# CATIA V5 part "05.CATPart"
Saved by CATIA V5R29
Part number: 05
Bounding box of the stored display mesh (mm): x -7.47 to 7.47, y 0 to 80, z -7.47 to 7.47
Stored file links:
  C:\Users\FERIDUN\Desktop\montaj3\05.CATPart
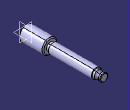
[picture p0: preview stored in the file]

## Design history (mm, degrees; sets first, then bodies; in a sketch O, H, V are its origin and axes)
Body1 (main body)
  Sketch1 on yz-plane, origin (0, 0, 0), H (0, 1, 0), V (0, 0, 1)
    line L1 (0, 0) -> (0, 7.5)
    line L2 (0, 7.5) -> (25, 7.5)
    line L3 (25, 7.5) -> (25, 4)
    line L4 (25, 4) -> (28, 4)
    line L5 (28, 4) -> (28, 5)
    arc A1 centre (76, 4) radius 2 from (74, 4) to (78, 4) ccw
    point P7 (76, 4)
    line L6 (78, 4) -> (80, 4)
    line L7 (80, 4) -> (80, 0)
    point P10 (80, 0)
    axis line L8 (0, 0) -> (163.2204, 0)
    line L9 (74, 4) -> (72, 4)
    line L10 (72, 4) -> (72, 5)
    line L11 (72, 5) -> (28, 5)
    length L2 = 25
    length L4 = 3
    distance L3 L7 = 55
    radius about axis L2 L8 = 7.5
    radius about axis L4 L8 = 4
    radius A1 = 2
    radius about axis L6 L8 = 4
    distance L10 L7 = 8
    radius about axis L11 L8 = 5
    distance P7 L10 = 4
    vertical: L1 V, L3 V, L5 V, L7 V, L10 V
    horizontal: L2 H, L4 H, L6 H, L8 H, L9 H, L11 H
    coincidence: P10 H, P7 L6, L6 L9
  Shaft1: profile Sketch1, axis edge of Sketch1, angle 360
  Chamfer1: length 1, angle 45, on edge [face of Shaft1 from Sketch1.L1 | face of Shaft1 from Sketch1.L2]; edge [face of Shaft1 from Sketch1.L2 | face of Shaft1 from Sketch1.L3]
  Chamfer2: length 0.5, angle 45, on edge [face of Shaft1 from Sketch1.L6 | face of Shaft1 from Sketch1.L7]
  Thread1: "M10", diameter 10, depth 44, pitch 1.5, on face of Shaft1 from Sketch1.L11, from face of Shaft1 from Sketch1.L5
